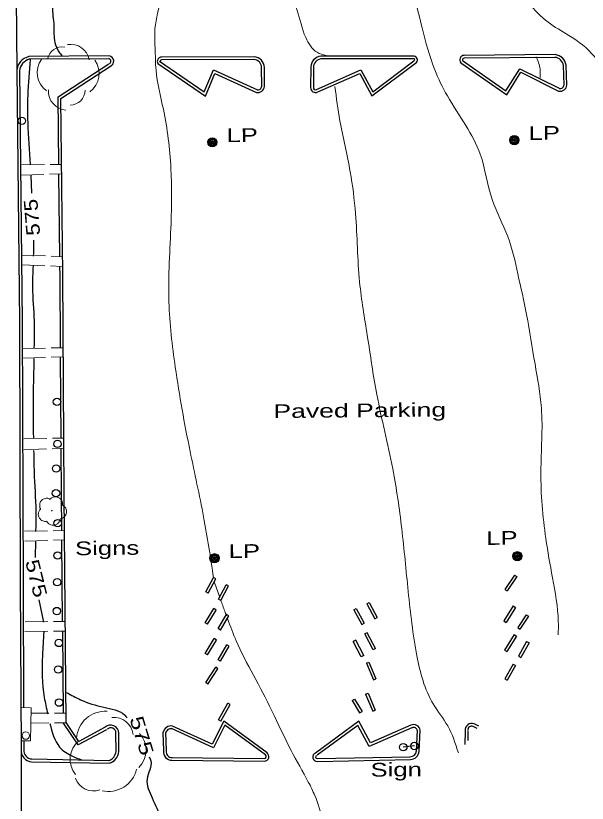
# Model space of a CAD drawing. Extents: x 2361708 to 2370558, y 6977955 to 6991887.
# Drawn here: x 2369162.4 to 2369362.7, y 6989808.4 to 6990084.2 of the extents above; entities that cross this region are included whole.
import ezdxf
from ezdxf.enums import TextEntityAlignment as Align

# ---------------------------------------------------------------- set-up
doc = ezdxf.new("R2010")
doc.units = 0
doc.header["$LTSCALE"] = 1.9
for name, color, linetype, lineweight in [('2', 7, 'Continuous', 25), ('20', 7, 'Continuous', 25), ('21', 7, 'Continuous', 25), ('28', 7, 'Continuous', 13), ('29', 7, 'Continuous', 13), ('31', 7, 'Continuous', 13), ('35', 7, 'Continuous', 13), ('9', 7, 'Continuous', 13)]:
    doc.layers.add(name, color=color, linetype=linetype, lineweight=lineweight)

msp = doc.modelspace()

# ---------------------------------------------------------------- linework, layer by layer
at = {"layer": '2'}
for p, q in [((2369162.397, 6990099.787), (2369162.748, 6990065.009)), ((2369195.111, 6990070.147), (2369166.991, 6990069.919)), ((2369301.997, 6990070.055), (2369269.355, 6990070.084)), ((2369351.454, 6990070.605), (2369319.545, 6990070.312)), ((2369195.12, 6990069.187), (2369167, 6990068.96)), ((2369245.956, 6990069.871), (2369213.466, 6990069.712)), ((2369245.965, 6990068.911), (2369213.475, 6990068.752)), ((2369301.996, 6990069.095), (2369269.354, 6990069.124)), ((2369351.463, 6990069.645), (2369319.554, 6990069.352)), ((2369248.585, 6990059.446), (2369248.562, 6990066.106)), ((2369249.545, 6990059.445), (2369249.522, 6990066.105)), ((2369265.76, 6990066.31), (2369265.739, 6990059.119)), ((2369266.72, 6990066.309), (2369266.699, 6990059.118)), ((2369354.595, 6990059.925), (2369354.329, 6990066.912)), ((2369355.555, 6990059.964), (2369355.289, 6990066.952)), ((2369177.859, 6989999.819), (2369177.555, 6990028.598)), ((2369178.314, 6989936.271), (2369178.125, 6989964.51)), ((2369178.834, 6989872.193), (2369178.585, 6989900.432)), ((2369337.168, 6989888.29), (2369333.836, 6989883.259)), ((2369337.168, 6989888.29), (2369337.974, 6989887.758)), ((2369228.97, 6989882.38), (2369231.722, 6989887.397)), ((2369229.814, 6989881.918), (2369232.566, 6989886.935)), ((2369232.566, 6989886.935), (2369231.722, 6989887.397)), ((2369337.974, 6989887.758), (2369334.641, 6989882.726)), ((2369233.444, 6989879.863), (2369236.146, 6989884.929)), ((2369234.288, 6989879.411), (2369236.99, 6989884.477)), ((2369236.99, 6989884.477), (2369236.146, 6989884.929)), ((2369333.836, 6989883.259), (2369334.641, 6989882.726)), ((2369229.814, 6989881.918), (2369228.97, 6989882.38)), ((2369234.288, 6989879.411), (2369233.444, 6989879.863)), ((2369285.392, 6989878.187), (2369286.238, 6989878.645)), ((2369285.392, 6989878.187), (2369288.242, 6989872.944)), ((2369286.238, 6989878.645), (2369289.088, 6989873.402)), ((2369336.731, 6989877.506), (2369333.401, 6989872.254)), ((2369337.546, 6989876.993), (2369334.216, 6989871.742)), ((2369336.731, 6989877.506), (2369337.546, 6989876.993)), ((2369228.802, 6989871.568), (2369231.845, 6989876.567)), ((2369229.627, 6989871.066), (2369232.67, 6989876.065)), ((2369232.67, 6989876.065), (2369231.845, 6989876.567)), ((2369233.282, 6989869.551), (2369236.274, 6989874.55)), ((2369237.099, 6989874.058), (2369236.274, 6989874.55)), ((2369280.832, 6989876.074), (2369281.667, 6989876.541)), ((2369280.832, 6989876.074), (2369283.681, 6989870.991)), ((2369281.667, 6989876.541), (2369284.516, 6989871.459)), ((2369341.331, 6989874.419), (2369338.324, 6989869.901)), ((2369341.331, 6989874.419), (2369342.126, 6989873.887)), ((2369229.627, 6989871.066), (2369228.802, 6989871.568)), ((2369234.107, 6989869.059), (2369237.099, 6989874.058)), ((2369283.681, 6989870.991), (2369284.516, 6989871.459)), ((2369288.242, 6989872.944), (2369289.088, 6989873.402)), ((2369333.401, 6989872.254), (2369334.216, 6989871.742)), ((2369342.126, 6989873.887), (2369339.119, 6989869.368)), ((2369234.107, 6989869.059), (2369233.282, 6989869.551)), ((2369338.324, 6989869.901), (2369339.119, 6989869.368)), ((2369179.111, 6989839.984), (2369178.869, 6989868.553)), ((2369228.755, 6989860.807), (2369231.925, 6989866.048)), ((2369232.75, 6989865.556), (2369231.925, 6989866.048)), ((2369285.568, 6989868.118), (2369284.722, 6989867.67)), ((2369287.665, 6989862.128), (2369284.722, 6989867.67)), ((2369288.511, 6989862.576), (2369285.568, 6989868.118)), ((2369337.037, 6989867.458), (2369333.688, 6989862.026)), ((2369337.852, 6989866.956), (2369334.503, 6989861.524)), ((2369337.037, 6989867.458), (2369337.852, 6989866.956)), ((2369229.579, 6989860.315), (2369232.75, 6989865.556)), ((2369233.346, 6989858.631), (2369236.326, 6989863.84)), ((2369234.18, 6989858.159), (2369237.161, 6989863.368)), ((2369237.161, 6989863.368), (2369236.326, 6989863.84)), ((2369281.553, 6989865.49), (2369280.707, 6989865.042)), ((2369283.508, 6989859.688), (2369280.707, 6989865.042)), ((2369284.354, 6989860.137), (2369281.553, 6989865.49)), ((2369341.43, 6989865.03), (2369338.579, 6989859.852)), ((2369342.275, 6989864.568), (2369339.424, 6989859.391)), ((2369341.43, 6989865.03), (2369342.275, 6989864.568)), ((2369229.579, 6989860.315), (2369228.755, 6989860.807)), ((2369288.511, 6989862.576), (2369287.665, 6989862.128)), ((2369333.688, 6989862.026), (2369334.503, 6989861.524)), ((2369234.18, 6989858.159), (2369233.346, 6989858.631)), ((2369284.354, 6989860.137), (2369283.508, 6989859.688)), ((2369285.309, 6989857.465), (2369286.196, 6989857.834)), ((2369286.196, 6989857.834), (2369288.652, 6989851.987)), ((2369338.579, 6989859.852), (2369339.424, 6989859.391)), ((2369228.961, 6989850.659), (2369232.47, 6989856.042)), ((2369229.766, 6989850.137), (2369233.276, 6989855.52)), ((2369233.276, 6989855.52), (2369232.47, 6989856.042)), ((2369285.309, 6989857.465), (2369287.765, 6989851.619)), ((2369336.776, 6989857.075), (2369333.784, 6989851.977)), ((2369337.6, 6989856.593), (2369334.609, 6989851.495)), ((2369336.776, 6989857.075), (2369337.6, 6989856.593)), ((2369229.766, 6989850.137), (2369228.961, 6989850.659)), ((2369287.765, 6989851.619), (2369288.652, 6989851.987)), ((2369333.784, 6989851.977), (2369334.609, 6989851.495)), ((2369285.013, 6989846.542), (2369285.9, 6989846.92)), ((2369285.9, 6989846.92), (2369288.406, 6989841.024)), ((2369280.344, 6989844.328), (2369281.169, 6989844.825)), ((2369280.344, 6989844.328), (2369282.925, 6989840.042)), ((2369281.169, 6989844.825), (2369283.751, 6989840.54)), ((2369285.013, 6989846.542), (2369287.52, 6989840.645)), ((2369233.456, 6989837.621), (2369236.741, 6989843.422)), ((2369234.29, 6989837.149), (2369237.575, 6989842.95)), ((2369237.575, 6989842.95), (2369236.741, 6989843.422)), ((2369282.925, 6989840.042), (2369283.751, 6989840.54)), ((2369287.52, 6989840.645), (2369288.406, 6989841.024)), ((2369234.29, 6989837.149), (2369233.456, 6989837.621)), ((2369324.671, 6989835.349), (2369323.114, 6989836.144)), ((2369197.55, 6989826.479), (2369197.519, 6989832.898)), ((2369198.51, 6989826.488), (2369198.479, 6989832.908)), ((2369213.968, 6989833.075), (2369214.207, 6989826.827)), ((2369214.928, 6989833.114), (2369215.167, 6989826.866)), ((2369302.834, 6989826.65), (2369303.213, 6989834.014)), ((2369303.794, 6989826.6), (2369304.174, 6989833.964)), ((2369319.918, 6989833.693), (2369319.772, 6989829.012)), ((2369320.878, 6989833.663), (2369320.779, 6989830.412)), ((2369324.16, 6989834.534), (2369322.682, 6989835.29)), ((2369165.225, 6989830.011), (2369165.241, 6989827.281)), ((2369164.281, 6989827.272), (2369164.266, 6989791)), ((2369268.087, 6989824.01), (2369300.672, 6989824.65)), ((2369167.973, 6989822.927), (2369195.109, 6989822.375)), ((2369167.993, 6989823.887), (2369195.13, 6989823.335)), ((2369217.15, 6989823.435), (2369249.615, 6989823.114)), ((2369217.16, 6989824.395), (2369249.626, 6989824.074)), ((2369268.106, 6989823.05), (2369300.691, 6989823.69))]:
    msp.add_line(p, q, dxfattribs=at)
for points in [[(2369177.512, 6990032.128), (2369177.256, 6990055.806), (2369195.066, 6990067.397)], [(2369212.247, 6990067.471), (2369228.846, 6990056.078), (2369232.201, 6990064.01), (2369246.755, 6990057.378)], [(2369212.789, 6990068.265), (2369228.422, 6990057.534), (2369231.698, 6990065.295), (2369247.156, 6990058.252)], [(2369267.855, 6990058.439), (2369283.352, 6990065.227), (2369287.544, 6990057.606), (2369301.932, 6990068.404)], [(2369268.244, 6990057.563), (2369282.933, 6990063.993), (2369287.238, 6990056.174), (2369302.509, 6990067.639)], [(2369318.43, 6990067.721), (2369334.487, 6990056.523), (2369339.382, 6990064.41), (2369352.635, 6990057.856)], [(2369318.982, 6990068.506), (2369334.204, 6990057.89), (2369339.03, 6990065.657), (2369353.057, 6990058.72)], [(2369162.748, 6990065.009), (2369163.717, 6989976.874), (2369164.001, 6989885.072), (2369164.281, 6989827.272)], [(2369163.708, 6990065.018), (2369164.677, 6989976.883), (2369164.961, 6989885.072), (2369165.173, 6989841.781)], [(2369193.749, 6989834.983), (2369184.545, 6989830.065), (2369180.102, 6989836.683), (2369179.401, 6989916.61), (2369178.888, 6989993.639), (2369178.221, 6990055.286), (2369195.595, 6990066.592)], [(2369178.104, 6989967.83), (2369177.928, 6989993.63), (2369177.903, 6989996.29)], [(2369178.553, 6989903.852), (2369178.441, 6989916.601), (2369178.34, 6989932.531)], [(2369194.197, 6989834.137), (2369184.227, 6989828.812), (2369179.145, 6989836.384), (2369179.144, 6989836.454)], [(2369249.884, 6989825.287), (2369235.674, 6989835.712), (2369231.649, 6989827.813), (2369216.974, 6989834.504)], [(2369250.456, 6989826.062), (2369235.33, 6989837.159), (2369231.207, 6989829.069), (2369217.377, 6989835.378)], [(2369300.867, 6989835.693), (2369286.725, 6989829.527), (2369282.583, 6989837.088), (2369267.488, 6989825.974)], [(2369301.256, 6989834.816), (2369286.307, 6989828.293), (2369282.267, 6989835.666), (2369268.056, 6989825.199)]]:
    msp.add_lwpolyline(points, dxfattribs=at)
for centre, radius, start, end in [((2369194.878, 6990068.306), 1.858, 292.69229, 82.79296), ((2369269.85, 6990066.014), 4.1, 96.94127, 175.86278), ((2369301.886, 6990068.768), 1.289, 298.946, 85.07172), ((2369319.515, 6990068.79), 1.522, 88.86241, 224.57902), ((2369351.005, 6990066.295), 4.334, 8.72132, 84.05402), ((2369168.275, 6990064.521), 5.549, 103.37788, 174.95332), ((2369168.275, 6990064.521), 4.589, 103.37788, 174.95332), ((2369194.878, 6990068.306), 0.898, 292.69229, 82.79296), ((2369213.439, 6990068.277), 1.435, 88.95187, 214.08323), ((2369213.439, 6990068.277), 0.475, 88.95187, 214.08323), ((2369245.706, 6990066.063), 2.856, 0.63209, 86.25171), ((2369245.706, 6990066.063), 3.816, 0.63209, 86.25171), ((2369269.85, 6990066.014), 3.14, 96.94127, 175.86278), ((2369301.886, 6990068.768), 0.329, 298.946, 85.07172), ((2369319.515, 6990068.79), 0.562, 88.86241, 224.57902), ((2369351.005, 6990066.295), 3.374, 8.72132, 84.05402), ((2369247.243, 6990059.634), 2.308, 257.78349, 355.30971), ((2369247.243, 6990059.634), 1.348, 257.78349, 355.30971), ((2369267.41, 6990059.016), 1.674, 176.47443, 299.85101), ((2369267.41, 6990059.016), 0.714, 176.47443, 299.85101), ((2369353.166, 6990060.197), 2.401, 257.22896, 354.42282), ((2369353.166, 6990060.197), 1.441, 257.22896, 354.42282), ((2369195.699, 6989833), 2.782, 358.0916, 134.526), ((2369301.856, 6989833.553), 2.355, 10.05007, 114.78979), ((2369322.173, 6989834.064), 2.283, 65.64783, 189.32825), ((2369195.699, 6989833), 1.822, 358.0916, 134.526), ((2369216.78, 6989832.588), 2.853, 77.93936, 170.17361), ((2369216.78, 6989832.588), 1.893, 77.93936, 170.17361), ((2369301.856, 6989833.553), 1.395, 10.05007, 114.78979), ((2369322.173, 6989834.064), 1.323, 65.64783, 189.32825), ((2369168.192, 6989826.855), 3.933, 173.90925, 266.80021), ((2369168.192, 6989826.855), 2.973, 173.90925, 266.80021), ((2369193.92, 6989826.821), 3.642, 284.97738, 355.84544), ((2369193.92, 6989826.821), 4.602, 284.97738, 355.84544), ((2369217.154, 6989826.411), 2.976, 171.96148, 269.92315), ((2369217.154, 6989826.411), 2.016, 171.96148, 269.92315), ((2369249.459, 6989824.751), 0.684, 275.42875, 52.73319), ((2369249.459, 6989824.751), 1.645, 275.42875, 52.73319), ((2369268.006, 6989824.557), 1.509, 110.07796, 273.78521), ((2369268.006, 6989824.557), 0.549, 110.07796, 273.78521), ((2369300.546, 6989826.954), 2.307, 272.54819, 353.78518), ((2369300.546, 6989826.954), 3.267, 272.54819, 353.78518)]:
    msp.add_arc(centre, radius, start, end, dxfattribs=at)
at = {"layer": '20'}
for centre, radius in [((2369164.546, 6990047.415), 1.3), ((2369231.29, 6990039.91), 1.6), ((2369231.29, 6990039.91), 1.3), ((2369231.29, 6990039.91), 1), ((2369231.29, 6990039.91), 0.539), ((2369231.29, 6990039.91), 0.192), ((2369337.158, 6990040.658), 1.6), ((2369337.158, 6990040.658), 1.3), ((2369337.158, 6990040.658), 1), ((2369337.158, 6990040.658), 0.539), ((2369337.158, 6990040.658), 0.192), ((2369338.186, 6989894.911), 1.6), ((2369338.186, 6989894.911), 1.3), ((2369232.047, 6989894.21), 1.6), ((2369232.047, 6989894.21), 1.3), ((2369232.047, 6989894.21), 1), ((2369232.047, 6989894.21), 0.539), ((2369232.047, 6989894.21), 0.192), ((2369338.186, 6989894.911), 1), ((2369338.186, 6989894.911), 0.539), ((2369338.186, 6989894.911), 0.192)]:
    msp.add_circle(centre, radius, dxfattribs=at)
at = {"layer": '21'}
msp.add_line((2369302.127, 6989828.444), (2369298.22, 6989828.027), dxfattribs=at)
for centre in [(2369176.843, 6989948.997), (2369177.033, 6989934.249), (2369176.565, 6989925.634), (2369176.497, 6989917.013), (2369177.087, 6989906.498), (2369177.075, 6989895.167), (2369176.924, 6989885.795), (2369176.781, 6989875.703), (2369177.527, 6989864.54), (2369177.305, 6989855.237), (2369177.586, 6989843.629), (2369298.211, 6989828.016), (2369302.118, 6989828.433)]:
    msp.add_circle(centre, 1.3, dxfattribs=at)
at = {"layer": '28'}
for p, q in [((2369172.482, 6990032.09), (2369164.482, 6990031.994)), ((2369178.481, 6990032.167), (2369174.482, 6990032.119)), ((2369172.195, 6990028.637), (2369164.197, 6990028.391)), ((2369178.193, 6990028.814), (2369174.194, 6990028.696)), ((2369172.796, 6990000.091), (2369164.804, 6990000.325)), ((2369178.798, 6989999.918), (2369174.797, 6990000.03)), ((2369172.609, 6989996.669), (2369164.615, 6989996.973)), ((2369178.611, 6989996.437), (2369174.61, 6989996.588)), ((2369172.773, 6989967.82), (2369164.774, 6989967.713)), ((2369178.773, 6989967.907), (2369174.774, 6989967.849)), ((2369172.805, 6989964.53), (2369164.807, 6989964.303)), ((2369178.803, 6989964.707), (2369174.805, 6989964.589)), ((2369173.285, 6989936.193), (2369165.286, 6989936.037)), ((2369179.284, 6989936.31), (2369175.285, 6989936.232)), ((2369173.21, 6989932.472), (2369165.213, 6989932.136)), ((2369179.208, 6989932.709), (2369175.209, 6989932.551)), ((2369173.483, 6989903.783), (2369165.484, 6989903.687)), ((2369179.483, 6989903.86), (2369175.483, 6989903.812)), ((2369173.625, 6989900.425), (2369165.627, 6989900.199)), ((2369179.624, 6989900.592), (2369175.625, 6989900.484)), ((2369173.685, 6989872.034), (2369165.686, 6989871.978)), ((2369179.685, 6989872.081), (2369175.686, 6989872.053)), ((2369173.607, 6989868.633), (2369165.607, 6989868.586)), ((2369179.608, 6989868.67), (2369175.608, 6989868.642)), ((2369173.991, 6989839.935), (2369167.681, 6989839.885)), ((2369179.991, 6989839.982), (2369175.991, 6989839.954)), ((2369173.944, 6989836.494), (2369167.714, 6989836.415)), ((2369179.943, 6989836.572), (2369175.944, 6989836.524))]:
    msp.add_line(p, q, dxfattribs=at)
at = {"layer": '29'}
msp.add_circle((2369175.056, 6989910.869), 0.1, dxfattribs=at)
for centre, radius, start, end in [((2369178.72, 6990068.08), 5.275, 79.84589, 169.84589), ((2369181.683, 6990067.609), 6.601, 10.17036, 100.17036), ((2369177.847, 6990064.244), 7.917, 143.53446, 233.53446), ((2369183.692, 6990063.991), 7.917, 306.10039, 36.10039), ((2369180.453, 6990057.769), 6.601, 176.10916, 266.10916), ((2369181.417, 6990058.189), 5.275, 270.07351, 0.07351), ((2369193.754, 6989830.546), 10.071, 86.34847, 176.34847), ((2369196.831, 6989831.752), 6.71, 6.54777, 96.54777), ((2369199.688, 6989826.945), 8.396, 313.97089, 43.97089), ((2369189.845, 6989823.81), 8.396, 129.55881, 219.55881), ((2369194.904, 6989822.567), 10.071, 256.99592, 346.99592), ((2369189.654, 6989819.383), 6.71, 199.40835, 289.40835)]:
    msp.add_arc(centre, radius, start, end, dxfattribs=at)
for points in [[(2369171.09, 6989911.441), (2369171.11, 6989911.451), (2369171.029, 6989911.52), (2369170.793, 6989912.148), (2369170.831, 6989913.428), (2369171.719, 6989914.727), (2369173.024, 6989915.21), (2369174.146, 6989915.02), (2369174.377, 6989914.892), (2369174.448, 6989914.893), (2369174.497, 6989914.933), (2369174.844, 6989915.227), (2369175.71, 6989915.675), (2369176.921, 6989915.607), (2369178.037, 6989915.017), (2369178.77, 6989913.594), (2369178.778, 6989912.734)], [(2369178.768, 6989912.754), (2369179.908, 6989911.695), (2369180.193, 6989910.107), (2369179.486, 6989908.781), (2369178.831, 6989908.234), (2369178.163, 6989908.018), (2369178.013, 6989908.007), (2369177.994, 6989907.897), (2369177.673, 6989906.993), (2369176.134, 6989905.828), (2369174.241, 6989906.111), (2369173.342, 6989907.052), (2369173.27, 6989907.182), (2369173.151, 6989907.16), (2369171.939, 6989907.279), (2369170.67, 6989908.277), (2369170.325, 6989909.914), (2369170.695, 6989910.937), (2369171.02, 6989911.38), (2369171.09, 6989911.431)]]:
    msp.add_spline(points, degree=3, dxfattribs=at)
at = {"layer": '31', "lineweight": 25}
for p, q in [((2369167.707, 6990028.394), (2369167.937, 6990022.096)), ((2369169.355, 6989900.344), (2369169.192, 6989894.462)), ((2369170.523, 6989879.594), (2369172.127, 6989871.829))]:
    msp.add_line(p, q, dxfattribs=at)
for points in [[(2369177.338, 6990095.57), (2369175.236, 6990087.379), (2369175.759, 6990080.714), (2369176.085, 6990074.887), (2369177.516, 6990071.63), (2369178.58, 6990070.13)], [(2369167.472, 6990068.844), (2369166.61, 6990056.375), (2369166.581, 6990046.795), (2369167.462, 6990032.032)], [(2369168.603, 6990005.622), (2369168.643, 6990004.662), (2369168.527, 6990000.051)], [(2369168.449, 6989996.63), (2369168.261, 6989989.118), (2369168.812, 6989977.362), (2369168.783, 6989967.852)], [(2369168.768, 6989964.211), (2369168.523, 6989951.058), (2369168.573, 6989936.388)], [(2369168.675, 6989931.899), (2369168.892, 6989922.76), (2369169.454, 6989908.955), (2369169.345, 6989903.564)], [(2369172.25, 6989868.39), (2369171.779, 6989860.085), (2369172.388, 6989845.46), (2369173.613, 6989839.711)], [(2369180.242, 6989847.165), (2369185.107, 6989844.621), (2369193.272, 6989842.019), (2369200.508, 6989839.297), (2369201.408, 6989838.286)], [(2369174.366, 6989836.279), (2369177.754, 6989828.081), (2369182.255, 6989824.883), (2369185.447, 6989823.593)], [(2369209.169, 6989824.579), (2369209.702, 6989823.224), (2369208.413, 6989816.762), (2369210.164, 6989810.328), (2369213.732, 6989803.241), (2369217.212, 6989799.055), (2369218.042, 6989797.993)]]:
    msp.add_spline(points, degree=3, dxfattribs=at)
at = {"layer": '35'}
msp.add_line((2369232.019, 6989885.65), (2369233.888, 6989880.507), dxfattribs=at)
for points in [[(2369211.576, 6990112.756), (2369210.491, 6990109.055), (2369212.073, 6990100.49), (2369213.089, 6990090.399), (2369211.19, 6990079.741), (2369211.234, 6990073.001), (2369211.569, 6990065.183), (2369214.13, 6990051.457), (2369216.786, 6990030.762), (2369216.81, 6990011.471), (2369216.082, 6989983.972), (2369218.32, 6989961.113), (2369223.51, 6989931.621), (2369228.229, 6989908.684), (2369231.721, 6989887.417)], [(2369269.666, 6990113.079), (2369264.7, 6990108.371), (2369259.41, 6990103.051), (2369258.304, 6990095.29), (2369261.042, 6990086.055), (2369264.012, 6990076.614), (2369268.032, 6990071.411), (2369271.153, 6990070.311)], [(2369300.207, 6990113.11), (2369299.591, 6990104.223), (2369301.431, 6990093.781), (2369304.823, 6990079.962), (2369309.263, 6990065.273), (2369313.669, 6990056.175), (2369320.089, 6990045.786), (2369325.174, 6990035.763), (2369329.336, 6990019.842), (2369334.85, 6990006.864), (2369338.374, 6989993.788), (2369341.42, 6989979.525), (2369344.385, 6989962.253), (2369346.622, 6989946.843), (2369346.444, 6989924.47), (2369348.167, 6989901.106), (2369350.528, 6989887.378), (2369352.544, 6989872.006), (2369352.519, 6989867.315)], [(2369329.751, 6990112.831), (2369330.813, 6990107.361), (2369336.376, 6990098.623), (2369342.271, 6990088.719), (2369348.956, 6990081.972), (2369356.19, 6990077.361), (2369365.171, 6990069.906), (2369369.828, 6990060.75), (2369371.621, 6990052.086), (2369373.623, 6990041.335), (2369375.195, 6990028.529), (2369375.677, 6990018.883), (2369377.474, 6990004.55), (2369378.626, 6989991.78), (2369379.222, 6989983.815)], [(2369344.801, 6990069.812), (2369346.161, 6990065.595), (2369346.163, 6990063.285), (2369346.093, 6990062.204)], [(2369274.247, 6990059.42), (2369276.031, 6990047.436), (2369279.611, 6990029.56), (2369281.47, 6990014.907), (2369282.919, 6989990.969), (2369285.607, 6989972.234), (2369288.944, 6989951.565), (2369294.532, 6989925.476), (2369297.671, 6989904.585), (2369299.951, 6989882.596), (2369303.016, 6989859.974), (2369308.676, 6989843.187), (2369313.77, 6989835.496), (2369317.53, 6989826.021)], [(2369234.237, 6989879.56), (2369235.654, 6989875.643), (2369236.259, 6989874.059)], [(2369236.649, 6989873.053), (2369239.663, 6989865.241), (2369245.698, 6989853.268), (2369252.146, 6989840.799), (2369258.889, 6989826.893), (2369264.935, 6989815.819), (2369267.21, 6989811.101), (2369270.092, 6989802.458), (2369271.521, 6989798.371)]]:
    msp.add_spline(points, degree=3, dxfattribs=at)
at = {"layer": '9'}
msp.add_lwpolyline([(2369164.352, 6989841.914), (2369167.772, 6989841.856), (2369167.593, 6989830.244), (2369164.352, 6989830.293)], dxfattribs=at)
msp.add_circle((2369165.905, 6989832.068), 1.3, dxfattribs=at)

# ---------------------------------------------------------------- texts
at = {"layer": '2', "width": 1.45}
msp.add_text('Paved Parking', height=4.8, rotation=0.545, dxfattribs=at).set_placement((2369252.721, 6989943.29))
at = {"layer": '20', "width": 1.4}
for s, p in [('  LP', (2369337.158, 6990040.658)), ('  LP', (2369231.29, 6990039.91)), ('  LP', (2369322.308, 6989898.819)), ('Signs', (2369183.205, 6989895.235)), ('  LP', (2369232.047, 6989894.21)), ('Sign', (2369286.758, 6989817.687))]:
    msp.add_text(s, height=4.8, rotation=0.545, dxfattribs=at).set_placement(p)
at = {"layer": '31'}
for rotation, width, p in [(94.553, 1.2, (2369170.45, 6990013.804)), (283.839, 1.25, (2369167.286, 6989886.572)), (286.956, 1.3, (2369204.287, 6989831.341))]:
    msp.add_text(' 575 ', height=4.8, rotation=rotation, dxfattribs=dict(at, width=width)).set_placement(p, align=Align.CENTER)

doc.saveas('drawing.dxf')
